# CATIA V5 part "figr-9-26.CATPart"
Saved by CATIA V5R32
Part number: Part1
Bounding box of the stored display mesh (mm): x -75 to 75, y -50 to 50, z 0 to 40
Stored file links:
  D:\PROJECTS\Project 2022\CATIA V5 6R 2022\Resources\Part Files\c09_catia_v5_6r2022_prt\c09_catia_v5_6r2022_prt\figr-9-26.CATPart
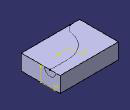
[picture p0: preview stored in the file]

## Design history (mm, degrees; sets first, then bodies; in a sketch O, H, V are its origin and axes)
Body1 (main body)
  Sketch1 on xy-plane, origin (0, 0, 0), H (1, 0, 0), V (0, 1, 0)
    line L1 (-75, 50) -> (75, 50)
    line L2 (75, 50) -> (75, -50)
    line L3 (75, -50) -> (-75, -50)
    line L4 (-75, -50) -> (-75, 50)
    axis line L5 (75, -50) -> (-75, 50)
    length L2 = 100
    length L3 = 150
    horizontal: L1 H, L3 H
    vertical: L2 V, L4 V
    midpoint: O L5
  Pad1: profile Sketch1, direction (0, 0, 1), length 40
  Sketch2 on face of Pad1, origin (75, 0, 0), H (0, 1, 0), V (0, 0, 1)
    arc A1 centre (24.1478, 40) radius 14.6047 from (9.543, 40) to (38.7525, 40) ccw
    point P1 (24.1478, 40)
    reference projected point E1 (24.1478, 40) from vertex of Sketch3
    line L1 (9.543, 40) -> (38.7525, 40)
    coincidence: P1 E1
    horizontal: L1 H
  Sketch3 on face of Pad1, origin (0, 0, 40), H (1, 0, 0), V (0, 1, 0)
    point P1 (75, 24.1478)
    line L1 (75, 24.1478) -> (28.6577, 24.1478)
    arc A1 centre (28.6577, -39.2062) radius 63.354 from (28.6577, 24.1478) to (-33.8383, -28.8149) ccw
    arc A2 centre (-62.192, -24.1005) radius 28.7429 from (-33.8383, -28.8149) to (-49.7271, -50) cw
    point P6 (-49.7271, -50)
    reference projected line E1 (75, -50) -> (75, 50) from edge [face of Pad1 | face of Pad1]
    reference projected line E2 (-75, -50) -> (75, -50) from edge [face of Pad1 | face of Pad1]
    horizontal: L1 H
    tangency: A1 L1, A2 A1
    coincidence: P1 E1, P6 E2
